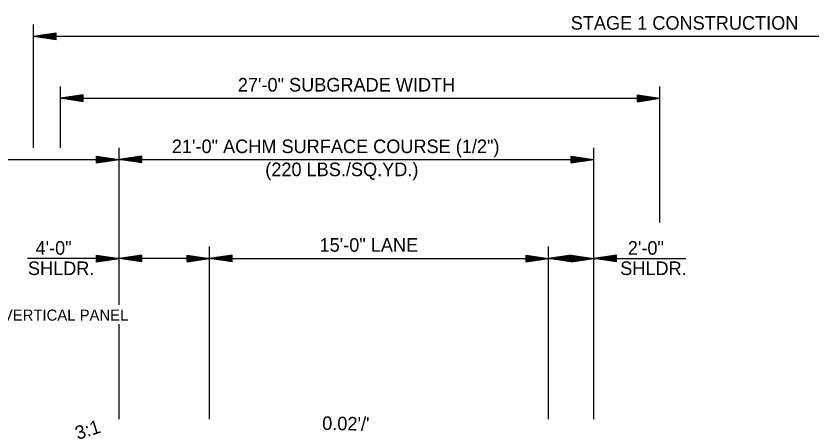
# Model space of a CAD drawing. Extents: x 2829243 to 2838161, y 467639 to 474695.
# Drawn here: x 2833939.1 to 2834291, y 469877.5 to 470061.1 of the extents above; entities that cross this region are included whole.
import ezdxf

# ---------------------------------------------------------------- set-up
doc = ezdxf.new("R2010")
doc.units = 0
doc.layers.add('R_Dimension', color=7, linetype='Continuous')
doc.layers.add('R_Draft', color=7, linetype='Continuous')

msp = doc.modelspace()

# ---------------------------------------------------------------- linework, layer by layer
at = {"layer": 'R_Dimension'}
for p, q in [((2833946.9, 470002.8), (2833946.9, 470057.26)), ((2833956.9, 470053.51), (2833946.9, 470052.01)), ((2834523.36, 470052.01), (2833946.9, 470052.01)), ((2833956.9, 470050.51), (2833946.9, 470052.01)), ((2833956.9, 470053.26), (2833948.57, 470052.01)), ((2833956.9, 470050.76), (2833948.57, 470052.01)), ((2833956.9, 470053.01), (2833950.29, 470052.01)), ((2833956.9, 470051.02), (2833950.29, 470052.01)), ((2833956.9, 470052.76), (2833951.95, 470052.01)), ((2833956.9, 470051.27), (2833951.95, 470052.01)), ((2833956.9, 470052.5), (2833953.65, 470052.01)), ((2833956.9, 470051.53), (2833953.65, 470052.01)), ((2833956.9, 470052.25), (2833955.32, 470052.01)), ((2833956.9, 470051.78), (2833955.32, 470052.01)), ((2833956.9, 470050.51), (2833956.9, 470053.51)), ((2833958.88, 470002.8), (2833958.88, 470029.91)), ((2834224.09, 469969.78), (2834224.09, 470029.91)), ((2833968.88, 470026.15), (2833958.88, 470024.65)), ((2833958.88, 470024.65), (2834224.09, 470024.65)), ((2833968.88, 470023.15), (2833958.88, 470024.65)), ((2833968.88, 470025.9), (2833960.55, 470024.65)), ((2833968.88, 470023.4), (2833960.55, 470024.65)), ((2833968.88, 470025.65), (2833962.27, 470024.65)), ((2833968.88, 470023.66), (2833962.27, 470024.65)), ((2833968.88, 470025.4), (2833963.93, 470024.65)), ((2833968.88, 470023.91), (2833963.93, 470024.65)), ((2833968.88, 470025.14), (2833965.63, 470024.65)), ((2833968.88, 470024.17), (2833965.63, 470024.65)), ((2833968.88, 470024.89), (2833967.3, 470024.65)), ((2833968.88, 470024.42), (2833967.3, 470024.65)), ((2833968.88, 470023.15), (2833968.88, 470026.15)), ((2834214.09, 470026.15), (2834224.09, 470024.65)), ((2834214.09, 470023.15), (2834214.09, 470026.15)), ((2834214.09, 470025.9), (2834222.42, 470024.65)), ((2834214.09, 470025.65), (2834220.7, 470024.65)), ((2834214.09, 470025.4), (2834219.04, 470024.65)), ((2834214.09, 470025.14), (2834217.34, 470024.65)), ((2834214.09, 470024.89), (2834215.67, 470024.65)), ((2834214.09, 470023.15), (2834224.09, 470024.65)), ((2834214.09, 470024.17), (2834217.34, 470024.65)), ((2834214.09, 470023.66), (2834220.7, 470024.65)), ((2834214.09, 470023.4), (2834222.42, 470024.65)), ((2834214.09, 470023.91), (2834219.04, 470024.65)), ((2834214.09, 470024.42), (2834215.67, 470024.65)), ((2833984.82, 469933.31), (2833984.82, 470002.8)), ((2834194.82, 469882.78), (2834194.82, 470002.8)), ((2833974.82, 469999.05), (2833984.82, 469997.55)), ((2833974.82, 469996.05), (2833974.82, 469999.05)), ((2833994.82, 469999.05), (2833984.82, 469997.55)), ((2833994.82, 469996.05), (2833994.82, 469999.05)), ((2834184.82, 469999.05), (2834194.82, 469997.55)), ((2834184.82, 469996.05), (2834184.82, 469999.05)), ((2833789.82, 469997.55), (2833984.82, 469997.55)), ((2833974.82, 469998.8), (2833983.15, 469997.55)), ((2833974.82, 469998.54), (2833981.43, 469997.55)), ((2833974.82, 469998.29), (2833979.77, 469997.55)), ((2833974.82, 469998.04), (2833978.07, 469997.55)), ((2833974.82, 469997.78), (2833976.4, 469997.55)), ((2833974.82, 469996.05), (2833984.82, 469997.55)), ((2833974.82, 469997.06), (2833978.07, 469997.55)), ((2833974.82, 469996.55), (2833981.43, 469997.55)), ((2833974.82, 469996.3), (2833983.15, 469997.55)), ((2833974.82, 469996.8), (2833979.77, 469997.55)), ((2833974.82, 469997.31), (2833976.4, 469997.55)), ((2833984.82, 469997.55), (2834194.82, 469997.55)), ((2833994.82, 469996.05), (2833984.82, 469997.55)), ((2833994.82, 469998.8), (2833986.49, 469997.55)), ((2833994.82, 469996.3), (2833986.49, 469997.55)), ((2833994.82, 469998.54), (2833988.21, 469997.55)), ((2833994.82, 469996.55), (2833988.21, 469997.55)), ((2833994.82, 469998.29), (2833989.88, 469997.55)), ((2833994.82, 469996.8), (2833989.88, 469997.55)), ((2833994.82, 469998.04), (2833991.57, 469997.55)), ((2833994.82, 469997.06), (2833991.57, 469997.55)), ((2833994.82, 469997.78), (2833993.24, 469997.55)), ((2833994.82, 469997.31), (2833993.24, 469997.55)), ((2834184.82, 469998.8), (2834193.15, 469997.55)), ((2834184.82, 469998.54), (2834191.43, 469997.55)), ((2834184.82, 469998.29), (2834189.77, 469997.55)), ((2834184.82, 469998.04), (2834188.07, 469997.55)), ((2834184.82, 469997.78), (2834186.4, 469997.55)), ((2834184.82, 469996.05), (2834194.82, 469997.55)), ((2834184.82, 469997.06), (2834188.07, 469997.55)), ((2834184.82, 469996.55), (2834191.43, 469997.55)), ((2834184.82, 469996.3), (2834193.15, 469997.55)), ((2834184.82, 469996.8), (2834189.77, 469997.55)), ((2834184.82, 469997.31), (2834186.4, 469997.55)), ((2834024.82, 469882.78), (2834024.82, 469959.04)), ((2834174.82, 469882.78), (2834174.82, 469959.04)), ((2834024.82, 469953.79), (2833944.25, 469953.79)), ((2833974.82, 469955.29), (2833984.82, 469953.79)), ((2833974.82, 469952.29), (2833974.82, 469955.29)), ((2833974.82, 469955.04), (2833983.15, 469953.79)), ((2833974.82, 469954.79), (2833981.43, 469953.79)), ((2833974.82, 469954.54), (2833979.77, 469953.79)), ((2833974.82, 469954.28), (2833978.07, 469953.79)), ((2833974.82, 469954.03), (2833976.4, 469953.79)), ((2833974.82, 469952.29), (2833984.82, 469953.79)), ((2833974.82, 469953.31), (2833978.07, 469953.79)), ((2833974.82, 469952.8), (2833981.43, 469953.79)), ((2833974.82, 469952.54), (2833983.15, 469953.79)), ((2833974.82, 469953.05), (2833979.77, 469953.79)), ((2833974.82, 469953.56), (2833976.4, 469953.79)), ((2833994.82, 469955.29), (2833984.82, 469953.79)), ((2833994.82, 469952.29), (2833984.82, 469953.79)), ((2833994.82, 469955.04), (2833986.49, 469953.79)), ((2833994.82, 469952.54), (2833986.49, 469953.79)), ((2833994.82, 469954.79), (2833988.21, 469953.79)), ((2833994.82, 469952.8), (2833988.21, 469953.79)), ((2833994.82, 469954.54), (2833989.88, 469953.79)), ((2833994.82, 469953.05), (2833989.88, 469953.79)), ((2833994.82, 469954.28), (2833991.57, 469953.79)), ((2833994.82, 469953.31), (2833991.57, 469953.79)), ((2833994.82, 469954.03), (2833993.24, 469953.79)), ((2833994.82, 469953.56), (2833993.24, 469953.79)), ((2833994.82, 469952.29), (2833994.82, 469955.29)), ((2834014.82, 469955.29), (2834024.82, 469953.79)), ((2834014.82, 469952.29), (2834014.82, 469955.29)), ((2834014.82, 469955.04), (2834023.15, 469953.79)), ((2834014.82, 469954.79), (2834021.43, 469953.79)), ((2834014.82, 469954.54), (2834019.77, 469953.79)), ((2834014.82, 469954.28), (2834018.07, 469953.79)), ((2834014.82, 469954.03), (2834016.4, 469953.79)), ((2834014.82, 469952.29), (2834024.82, 469953.79)), ((2834014.82, 469953.31), (2834018.07, 469953.79)), ((2834014.82, 469952.8), (2834021.43, 469953.79)), ((2834014.82, 469952.54), (2834023.15, 469953.79)), ((2834014.82, 469953.05), (2834019.77, 469953.79)), ((2834014.82, 469953.56), (2834016.4, 469953.79)), ((2834034.82, 469955.29), (2834024.82, 469953.79)), ((2834034.82, 469952.29), (2834024.82, 469953.79)), ((2834024.82, 469953.79), (2834174.82, 469953.79)), ((2834034.82, 469955.04), (2834026.49, 469953.79)), ((2834034.82, 469952.54), (2834026.49, 469953.79)), ((2834034.82, 469954.79), (2834028.21, 469953.79)), ((2834034.82, 469952.8), (2834028.21, 469953.79)), ((2834034.82, 469954.54), (2834029.88, 469953.79)), ((2834034.82, 469953.05), (2834029.88, 469953.79)), ((2834034.82, 469954.28), (2834031.57, 469953.79)), ((2834034.82, 469953.31), (2834031.57, 469953.79)), ((2834034.82, 469954.03), (2834033.24, 469953.79)), ((2834034.82, 469953.56), (2834033.24, 469953.79)), ((2834034.82, 469952.29), (2834034.82, 469955.29)), ((2834164.82, 469955.29), (2834174.82, 469953.79)), ((2834164.82, 469952.29), (2834164.82, 469955.29)), ((2834164.82, 469955.04), (2834173.15, 469953.79)), ((2834164.82, 469954.79), (2834171.43, 469953.79)), ((2834164.82, 469954.54), (2834169.77, 469953.79)), ((2834164.82, 469954.28), (2834168.07, 469953.79)), ((2834164.82, 469954.03), (2834166.4, 469953.79)), ((2834164.82, 469952.29), (2834174.82, 469953.79)), ((2834164.82, 469953.31), (2834168.07, 469953.79)), ((2834164.82, 469952.8), (2834171.43, 469953.79)), ((2834164.82, 469952.54), (2834173.15, 469953.79)), ((2834164.82, 469953.05), (2834169.77, 469953.79)), ((2834164.82, 469953.56), (2834166.4, 469953.79)), ((2834184.82, 469955.29), (2834174.82, 469953.79)), ((2834174.82, 469953.79), (2834235.58, 469953.79)), ((2834184.82, 469952.29), (2834174.82, 469953.79)), ((2834184.82, 469955.04), (2834176.49, 469953.79)), ((2834184.82, 469952.54), (2834176.49, 469953.79)), ((2834184.82, 469954.79), (2834178.21, 469953.79)), ((2834184.82, 469952.8), (2834178.21, 469953.79)), ((2834184.82, 469954.54), (2834179.88, 469953.79)), ((2834184.82, 469953.05), (2834179.88, 469953.79)), ((2834184.82, 469954.28), (2834181.57, 469953.79)), ((2834184.82, 469953.31), (2834181.57, 469953.79)), ((2834184.82, 469954.03), (2834183.24, 469953.79)), ((2834184.82, 469953.56), (2834183.24, 469953.79)), ((2834184.82, 469952.29), (2834184.82, 469955.29)), ((2834184.82, 469955.29), (2834194.82, 469953.79)), ((2834184.82, 469952.29), (2834184.82, 469955.29)), ((2834184.82, 469955.04), (2834193.15, 469953.79)), ((2834184.82, 469954.79), (2834191.43, 469953.79)), ((2834184.82, 469954.54), (2834189.77, 469953.79)), ((2834184.82, 469954.28), (2834188.07, 469953.79)), ((2834184.82, 469954.03), (2834186.4, 469953.79)), ((2834184.82, 469952.29), (2834194.82, 469953.79)), ((2834184.82, 469953.31), (2834188.07, 469953.79)), ((2834184.82, 469952.8), (2834191.43, 469953.79)), ((2834184.82, 469952.54), (2834193.15, 469953.79)), ((2834184.82, 469953.05), (2834189.77, 469953.79)), ((2834184.82, 469953.56), (2834186.4, 469953.79)), ((2834204.82, 469955.29), (2834194.82, 469953.79)), ((2834204.82, 469952.29), (2834194.82, 469953.79)), ((2834204.82, 469955.04), (2834196.49, 469953.79)), ((2834204.82, 469952.54), (2834196.49, 469953.79)), ((2834204.82, 469954.79), (2834198.21, 469953.79)), ((2834204.82, 469952.8), (2834198.21, 469953.79)), ((2834204.82, 469954.54), (2834199.88, 469953.79)), ((2834204.82, 469953.05), (2834199.88, 469953.79)), ((2834204.82, 469954.28), (2834201.57, 469953.79)), ((2834204.82, 469953.31), (2834201.57, 469953.79)), ((2834204.82, 469954.03), (2834203.24, 469953.79)), ((2834204.82, 469953.56), (2834203.24, 469953.79)), ((2834204.82, 469952.29), (2834204.82, 469955.29)), ((2833984.82, 469882.78), (2833984.82, 469924.74))]:
    msp.add_line(p, q, dxfattribs=at)

# ---------------------------------------------------------------- texts
for s, p in [('STAGE 1 CONSTRUCTION', (2834184.6, 470055.01)), ('4\'-0"', (2833947.77, 469955.47)), ('15\'-0" LANE', (2834073.46, 469956.79)), ('2\'-0"', (2834209.87, 469955.47)), ('SHLDR.', (2833944.4, 469946.47)), ('SHLDR.', (2834206.49, 469946.47))]:
    msp.add_text(s, height=6, dxfattribs=at).set_placement(p)
at = {"layer": 'R_Draft'}
for s, height, p in [('27\'-0" SUBGRADE WIDTH', 6, (2834037.29, 470027.65)), ('21\'-0" ACHM SURFACE COURSE (1/2")', 6, (2834008.09, 470000.41)), ('(220 LBS./SQ.YD.)', 6, (2834049.43, 469990.21)), ('STAGE 1: VERTICAL PANEL', 4.9184, (2833901.86, 469926.3))]:
    msp.add_text(s, height=height, dxfattribs=at).set_placement(p)
for s, rotation, p in [("0.02'/'", 358.8542, (2834074.57, 469877.99)), ('3:1', 17.5561, (2833966.42, 469873.53))]:
    msp.add_text(s, height=6, rotation=rotation, dxfattribs=at).set_placement(p)

doc.saveas('drawing.dxf')
